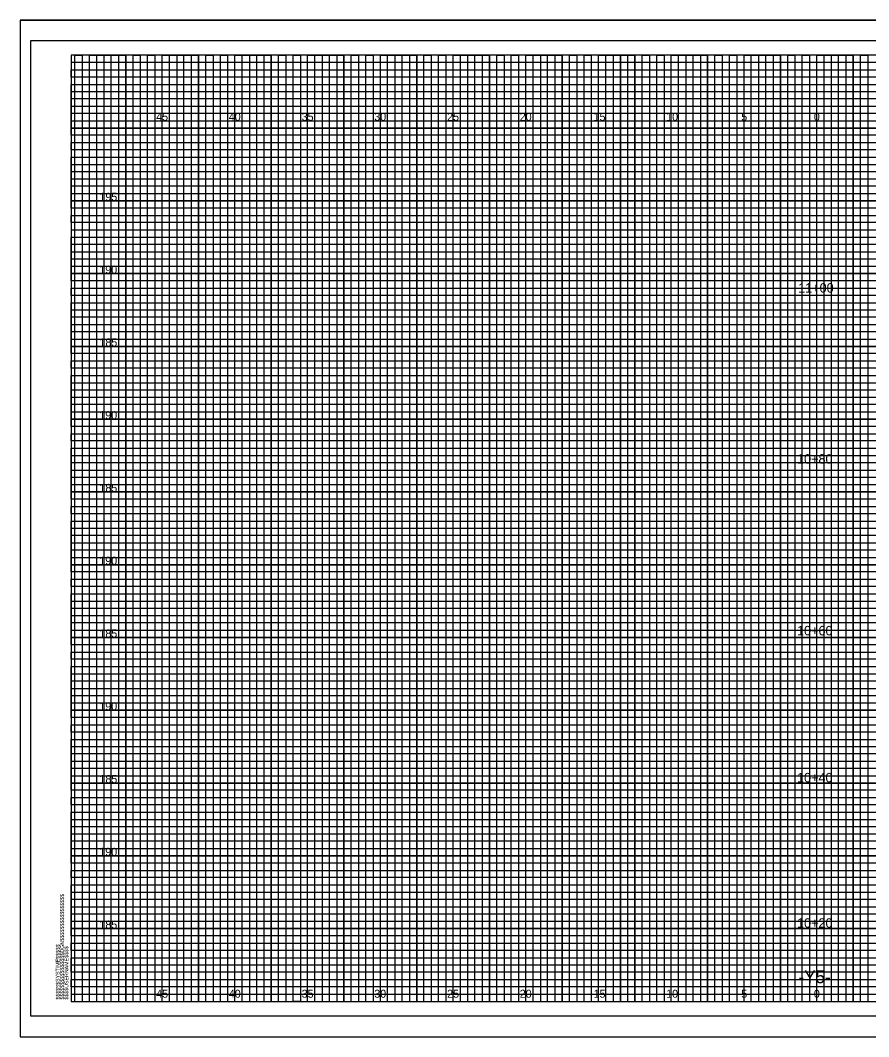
# Model space of a CAD drawing. Extents: x -4 to 103, y -2 to 67.
# Drawn here: x -3.5 to 54.8, y -2.4 to 67.4 of the extents above; entities that cross this region are included whole.
import ezdxf

# ---------------------------------------------------------------- set-up
doc = ezdxf.new("R2010")
doc.units = 0
for name, color, linetype in [('Exist XS Ground Line', 7, 'Continuous'), ('Old_Level_10', 7, 'Continuous'), ('Old_Level_16', 7, 'Continuous'), ('Old_Level_3', 7, 'Continuous'), ('Old_Level_4', 7, 'Continuous'), ('Old_Level_5', 7, 'Continuous'), ('Old_Level_8', 7, 'Continuous'), ('Prop XS Elevation Labels', 7, 'Continuous'), ('Prop XS EOT Tick Mark', 7, 'Continuous'), ('Prop XS Finish Grade Concrete', 7, 'Continuous'), ('Prop XS Subgrade Earthwork', 7, 'Continuous')]:
    doc.layers.add(name, color=color, linetype=linetype)

msp = doc.modelspace()

# ---------------------------------------------------------------- linework, layer by layer
at = {"layer": 'Exist XS Ground Line'}
msp.add_lwpolyline([(102.5, 65), (0, 65), (0, 0), (102.5, 0)], close=True, dxfattribs=at)
at = {"layer": 'Old_Level_10'}
for p, q in [((1.25, 0), (1.25, 65)), ((3.75, 0), (3.75, 65)), ((6.25, 0), (6.25, 65)), ((8.75, 0), (8.75, 65)), ((11.25, 0), (11.25, 65)), ((13.75, 0), (13.75, 65)), ((16.25, 0), (16.25, 65)), ((18.75, 0), (18.75, 65)), ((21.25, 0), (21.25, 65)), ((23.75, 0), (23.75, 65)), ((26.25, 0), (26.25, 65)), ((28.75, 0), (28.75, 65)), ((31.25, 0), (31.25, 65)), ((33.75, 0), (33.75, 65)), ((36.25, 0), (36.25, 65)), ((38.75, 0), (38.75, 65)), ((41.25, 0), (41.25, 65)), ((43.75, 0), (43.75, 65)), ((46.25, 0), (46.25, 65)), ((48.75, 0), (48.75, 65)), ((51.25, 0), (51.25, 65)), ((53.75, 0), (53.75, 65)), ((0, 62.5), (74.25, 62.5)), ((0, 60), (102.5, 60)), ((0, 57.5), (102.5, 57.5)), ((0, 55), (102.5, 55)), ((0, 52.5), (102.5, 52.5)), ((0, 50), (102.5, 50)), ((0, 47.5), (102.5, 47.5)), ((0, 45), (102.5, 45)), ((0, 42.5), (102.5, 42.5)), ((0, 40), (102.5, 40)), ((0, 37.5), (102.5, 37.5)), ((0, 35), (102.5, 35)), ((0, 32.5), (102.5, 32.5)), ((0, 30), (102.5, 30)), ((0, 27.5), (102.5, 27.5)), ((0, 25), (102.5, 25)), ((0, 22.5), (102.5, 22.5)), ((0, 20), (102.5, 20)), ((0, 17.5), (102.5, 17.5)), ((0, 15), (102.5, 15)), ((0, 12.5), (102.5, 12.5)), ((0, 10), (102.5, 10)), ((0, 7.5), (102.5, 7.5)), ((0, 5), (102.5, 5)), ((0, 2.5), (102.5, 2.5))]:
    msp.add_line(p, q, dxfattribs=at)
at = {"layer": 'Old_Level_3'}
for p, q in [((-3.5, 67.4), (103.4, 67.4)), ((-3.5, 67.4), (-3.5, -2.425)), ((-3.5, -2.425), (103.4, -2.425))]:
    msp.add_line(p, q, dxfattribs=at)
at = {"layer": 'Old_Level_4'}
msp.add_lwpolyline([(103, 66), (-2.8, 66), (-2.8, -1), (103, -1)], close=True, dxfattribs=at)
at = {"layer": 'Old_Level_5'}
msp.add_lwpolyline([(103.4, 67.4), (-3.5, 67.4), (-3.5, -2.425), (103.4, -2.425)], close=True, dxfattribs=at)
at = {"layer": 'Old_Level_8'}
for points in [[(1.25, 0), (1.25, 65), (3.75, 65), (3.75, 0), (6.25, 0), (6.25, 65), (8.75, 65), (8.75, 0), (11.25, 0), (11.25, 65), (13.75, 65), (13.75, 0), (16.25, 0), (16.25, 65), (18.75, 65), (18.75, 0), (21.25, 0), (21.25, 65), (23.75, 65), (23.75, 0), (26.25, 0), (26.25, 65), (28.75, 65), (28.75, 0), (31.25, 0), (31.25, 65), (33.75, 65), (33.75, 0), (36.25, 0), (36.25, 65), (38.75, 65), (38.75, 0), (41.25, 0), (41.25, 65), (43.75, 65), (43.75, 0), (46.25, 0), (46.25, 65), (48.75, 65), (48.75, 0), (51.25, 0), (51.25, 65), (53.75, 65), (53.75, 0)], [(102.5, 60), (0, 60), (0, 62.5), (74.25, 62.5)], [(102.5, 55), (0, 55), (0, 57.5), (102.5, 57.5)], [(102.5, 50), (0, 50), (0, 52.5), (102.5, 52.5)], [(102.5, 45), (0, 45), (0, 47.5), (102.5, 47.5)], [(102.5, 40), (0, 40), (0, 42.5), (102.5, 42.5)], [(102.5, 35), (0, 35), (0, 37.5), (102.5, 37.5)], [(102.5, 30), (0, 30), (0, 32.5), (102.5, 32.5)], [(102.5, 25), (0, 25), (0, 27.5), (102.5, 27.5)], [(102.5, 20), (0, 20), (0, 22.5), (102.5, 22.5)], [(102.5, 15), (0, 15), (0, 17.5), (102.5, 17.5)], [(102.5, 10), (0, 10), (0, 12.5), (102.5, 12.5)], [(102.5, 5), (0, 5), (0, 7.5), (102.5, 7.5)], [(0, 2.5), (102.5, 2.5)]]:
    msp.add_lwpolyline(points, dxfattribs=at)
at = {"layer": 'Prop XS Elevation Labels'}
for points in [[(0.25, 0), (0.25, 65), (0.75, 65), (0.75, 0), (1.75, 0), (1.75, 65), (2.25, 65), (2.25, 0), (2.75, 0), (2.75, 65), (3.25, 65), (3.25, 0), (4.25, 0), (4.25, 65), (4.75, 65), (4.75, 0), (5.25, 0), (5.25, 65), (5.75, 65), (5.75, 0), (6.75, 0), (6.75, 65), (7.25, 65), (7.25, 0), (7.75, 0), (7.75, 65), (8.25, 65), (8.25, 0), (9.25, 0), (9.25, 65), (9.75, 65), (9.75, 0), (10.25, 0), (10.25, 65), (10.75, 65), (10.75, 0), (11.75, 0), (11.75, 65), (12.25, 65), (12.25, 0), (12.75, 0), (12.75, 65), (13.25, 65), (13.25, 0), (14.25, 0), (14.25, 65), (14.75, 65), (14.75, 0), (15.75, 0), (15.25, 0), (15.25, 65), (15.75, 65), (15.75, 0), (16.75, 0), (16.75, 65), (17.25, 65), (17.25, 0), (17.75, 0), (17.75, 65), (18.25, 65), (18.25, 0), (19.25, 0), (19.25, 65), (19.75, 65), (19.75, 0), (20.25, 0), (20.25, 65), (20.75, 65), (20.75, 0), (21.75, 0), (21.75, 65), (22.25, 65), (22.25, 0), (22.75, 0), (22.75, 65), (23.25, 65), (23.25, 0), (24.25, 0), (24.25, 65), (24.75, 65), (24.75, 0), (25.25, 0), (25.25, 65), (25.75, 65), (25.75, 0), (26.75, 0), (26.75, 65), (27.25, 65), (27.25, 0), (27.75, 0), (27.75, 65), (28.25, 65), (28.25, 0), (29.25, 0), (29.25, 65), (29.75, 65), (29.75, 0), (30.25, 0), (30.25, 65), (30.75, 65), (30.75, 0)], [(30.75, 0), (31.75, 0), (31.75, 65), (32.25, 65), (32.25, 0), (32.75, 0), (32.75, 65), (33.25, 65), (33.25, 0), (34.25, 0), (34.25, 65), (34.75, 65), (34.75, 0), (35.25, 0), (35.25, 65), (35.75, 65), (35.75, 0), (36.75, 0), (36.75, 65), (37.25, 65), (37.25, 0), (37.75, 0), (37.75, 65), (37.75, 0)], [(38.25, 65), (38.25, 0), (39.25, 0), (39.25, 65), (39.75, 65), (39.75, 0), (40.25, 0), (40.25, 65), (40.75, 65), (40.75, 0), (41.75, 0), (41.75, 65), (42.25, 65), (42.25, 0), (42.75, 0), (42.75, 65), (43.25, 65), (43.25, 0), (43.75, 0), (44.25, 0), (44.25, 65), (44.75, 65), (44.75, 0), (45.25, 0), (45.25, 65), (45.75, 65), (45.75, 0), (46.75, 0), (46.75, 65), (47.25, 65), (47.25, 0), (47.75, 0), (47.75, 65), (48.25, 65), (48.25, 0), (49.25, 0), (49.25, 65), (49.75, 65), (49.75, 0), (50.25, 0), (50.25, 65), (50.75, 65), (50.75, 0), (51.75, 0), (51.75, 65), (52.25, 65), (52.25, 0), (52.75, 0), (52.75, 65), (53.25, 65), (53.25, 0), (54.25, 0), (54.25, 65), (54.75, 65), (54.75, 0), (55.25, 0)], [(0, 62), (0, 63), (74.25, 63), (74.25, 63.5), (0, 63.5), (0, 64), (74.25, 64), (74.25, 64.5), (0, 64.5)], [(102.5, 62), (0, 62)], [(102.5, 61), (0, 61), (0, 61.5), (102.5, 61.5)], [(102.5, 59.5), (0, 59.5), (0, 60.5), (102.5, 60.5)], [(102.5, 58.5), (0, 58.5), (0, 59), (102.5, 59)], [(102.5, 57), (0, 57), (0, 58), (102.5, 58)], [(102.5, 56), (0, 56), (0, 56.5), (102.5, 56.5)], [(102.5, 54.5), (0, 54.5), (0, 55.5), (102.5, 55.5)], [(102.5, 53.5), (0, 53.5), (0, 54), (102.5, 54)], [(0, 53), (102.5, 53)], [(102.5, 52), (0, 52)], [(102.5, 51), (0, 51), (0, 51.5), (102.5, 51.5)], [(102.5, 49.5), (0, 49.5), (0, 50.5), (102.5, 50.5)], [(102.5, 48.5), (0, 48.5), (0, 49), (102.5, 49)], [(102.5, 47), (0, 47), (0, 48), (102.5, 48)], [(102.5, 46), (0, 46), (0, 46.5), (102.5, 46.5)], [(102.5, 44.5), (0, 44.5), (0, 45.5), (102.5, 45.5)], [(102.5, 43.5), (0, 43.5), (0, 44), (102.5, 44)], [(102.5, 42), (0, 42), (0, 43), (102.5, 43)], [(102.5, 41), (0, 41), (0, 41.5), (102.5, 41.5)], [(102.5, 39.5), (0, 39.5), (0, 40.5), (102.5, 40.5)], [(102.5, 38.5), (0, 38.5), (0, 39), (102.5, 39)], [(102.5, 37), (0, 37), (0, 38), (102.5, 38)], [(102.5, 36), (0, 36), (0, 36.5), (102.5, 36.5)], [(102.5, 34.5), (0, 34.5), (0, 35.5), (102.5, 35.5)], [(102.5, 33.5), (0, 33.5), (0, 34), (102.5, 34)], [(102.5, 32), (0, 32), (0, 33), (102.5, 33)], [(102.5, 31), (0, 31), (0, 31.5)], [(0, 31.5), (102.5, 31.5)], [(102.5, 29.5), (0, 29.5), (0, 30.5), (102.5, 30.5)], [(102.5, 28.5), (0, 28.5), (0, 29), (102.5, 29)], [(102.5, 27), (0, 27), (0, 28), (102.5, 28)], [(102.5, 26), (0, 26), (0, 26.5), (102.5, 26.5)], [(102.5, 24.5), (0, 24.5), (0, 25.5), (102.5, 25.5)], [(102.5, 23.5), (0, 23.5), (0, 24), (102.5, 24)], [(102.5, 22), (0, 22), (0, 23), (102.5, 23)], [(102.5, 21), (0, 21), (0, 21.5), (102.5, 21.5)], [(102.5, 19.5), (0, 19.5), (0, 20.5), (102.5, 20.5)], [(102.5, 18.5), (0, 18.5), (0, 19), (102.5, 19)], [(102.5, 17), (0, 17), (0, 18), (102.5, 18)], [(102.5, 16), (0, 16), (0, 16.5), (102.5, 16.5)], [(102.5, 14.5), (0, 14.5), (0, 15.5), (102.5, 15.5)], [(102.5, 13.5), (0, 13.5), (0, 14), (102.5, 14)], [(102.5, 12), (0, 12), (0, 13), (102.5, 13)], [(102.5, 11), (0, 11), (0, 11.5), (102.5, 11.5)], [(102.5, 9.5), (0, 9.5), (0, 10.5), (102.5, 10.5)], [(102.5, 8.5), (0, 8.5), (0, 9), (102.5, 9)], [(102.5, 7), (0, 7), (0, 8), (102.5, 8)], [(102.5, 6), (0, 6), (0, 6.5), (102.5, 6.5)], [(102.5, 4.5), (0, 4.5), (0, 5.5), (102.5, 5.5)], [(102.5, 3.5), (0, 3.5), (0, 4), (102.5, 4)], [(102.5, 2), (0, 2), (0, 3), (102.5, 3)], [(102.5, 1), (0, 1), (0, 1.5), (102.5, 1.5)], [(0, 0.5), (102.5, 0.5)]]:
    msp.add_lwpolyline(points, dxfattribs=at)

# ---------------------------------------------------------------- texts
at = {"layer": 'Exist XS Ground Line'}
for s, p in [('$$$$$$$$$$$$$$$$DGN$$$$$$$$$$$$$$$$', (-0.5, 0.125)), ('$$$$$$SYSTIME$$$$$', (-0.7973, 0.1247)), ('$$$$USERNAME$$$$', (-0.2, 0.125))]:
    msp.add_text(s, height=0.2625, rotation=90, dxfattribs=at).set_placement(p)
at = {"layer": 'Old_Level_16'}
for s, p in [('45', (5.8399, 60.5)), ('40', (10.8313, 60.5)), ('35', (15.8399, 60.5)), ('30', (20.8313, 60.5)), ('25', (25.8399, 60.5)), ('20', (30.8313, 60.5)), ('15', (35.9058, 60.5)), ('10', (40.8971, 60.5)), ('5', (46.0574, 60.5)), ('0', (51.0488, 60.5)), ('0', (51.0488, 60.5)), ('45', (5.8399, 0.25)), ('40', (10.8313, 0.25)), ('35', (15.8399, 0.25)), ('30', (20.8313, 0.25)), ('25', (25.8399, 0.25)), ('20', (30.8313, 0.25)), ('15', (35.9058, 0.25)), ('10', (40.8971, 0.25)), ('5', (46.0574, 0.25)), ('0', (51.0488, 0.25)), ('0', (51.0488, 0.25))]:
    msp.add_text(s, height=0.55, dxfattribs=at).set_placement(p)
at = {"layer": 'Old_Level_8'}
msp.add_text('040397', height=0.0025, rotation=90, dxfattribs=at).set_placement((-0.0007, 64.9864))
at = {"layer": 'Prop XS EOT Tick Mark'}
for s, p in [('11+00', (49.9712, 48.6926)), ('10+80', (49.8934, 36.9413)), ('10+60', (49.8934, 25.1453)), ('10+40', (49.8934, 15.0462)), ('10+20', (49.8934, 5.0588))]:
    msp.add_text(s, height=0.65, dxfattribs=at).set_placement(p)
at = {"layer": 'Prop XS Finish Grade Concrete'}
for s, p in [('195', (1.9383, 55)), ('190', (1.9296, 50)), ('185', (1.9383, 45)), ('190', (1.9296, 40)), ('185', (1.9383, 35)), ('190', (1.9296, 30)), ('185', (1.9383, 25)), ('190', (1.9296, 20)), ('185', (1.9383, 15)), ('190', (1.9296, 10)), ('185', (1.9383, 5))]:
    msp.add_text(s, height=0.55, dxfattribs=at).set_placement(p)
at = {"layer": 'Prop XS Subgrade Earthwork'}
msp.add_text('-Y5-', height=0.875, dxfattribs=at).set_placement((49.9985, 1.25))

doc.saveas('drawing.dxf')
